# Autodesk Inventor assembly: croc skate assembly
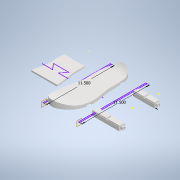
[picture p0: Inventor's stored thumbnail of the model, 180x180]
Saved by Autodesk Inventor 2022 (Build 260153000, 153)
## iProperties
Created: 2021-09
Part Number: croc skate assembly
Document SubType Name: Assembly
Designer: garre
Author: garre
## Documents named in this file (4)
- C:\Users\garre\3D Objects\croc skate assembly.iam
- C:\Users\garre\Documents\croc skate foot plate.ipt
- C:\Users\garre\3D Objects\croc skate axle holders.ipt
- C:\Users\garre\3D Objects\croc skate reinforcement plate.ipt
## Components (3 placed, 3 different names)
1. croc skate foot plate:1
2. croc skate axle holders:1
3. croc skate reinforcement plate:1
